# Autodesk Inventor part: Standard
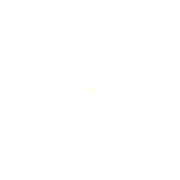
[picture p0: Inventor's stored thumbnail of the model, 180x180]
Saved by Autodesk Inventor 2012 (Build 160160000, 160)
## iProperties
Created: 2005-05
Part Number: Standard
Document SubType Name: Modeling
Designer: JWe
Density: 1 g/cm^3
Material: Default
Author: JWe
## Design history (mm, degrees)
sketch "Sketch1"
  geometry: 1 further point
  constraints: 1 other
